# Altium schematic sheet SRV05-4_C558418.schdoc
size 127 x 101 mm
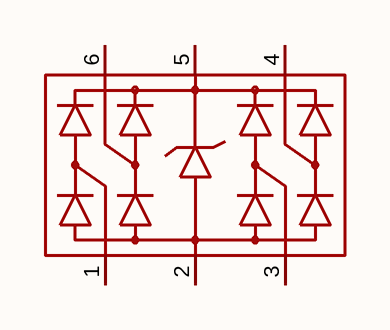
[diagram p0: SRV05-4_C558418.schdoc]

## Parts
D?  srv05-4_c558418  [SOT-23-6_L2.9-W1.6-P0.95-LS2.8-BL]  (value not drawn)

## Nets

Not connected (* = marked no-connect by the designer): D? 1 2 3 4 5 6

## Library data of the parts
D? = srv05-4_c558418: 极性:单向;反向截止电压(Vrwm):5V;钳位电压:20V;峰值脉冲电流(Ipp):3A;峰值脉冲功率(Ppp):60W;击穿电压:6V;; Manufacturer: TECH PUBLIC(台舟); AddInBom: yes; ModelId: 18da8f6c14a34920b3e136b5c401a119; ModelName: SOT-23-6_L2.9-W1.6-H1.5-LS2.8-P0.95; ModelTransform: 110.236,113.364,0,90,0,0,0.0005,0.0005,0; Polarity: 单向; Reverse Stand-Off Voltage (Vrwm): 5V; Clamping Voltage: 20V; Peak Pulse Current (Ipp): 3A; Peak Pulse Power Dissipation (Ppp): 60W; Voltage - Breakdown: 6V; Reverse Leakage Current (Ir): 500nA; Number of Channels: 四路; level of protection: IEC 61000-4-2；IEC 61000-4-4；IEC 61000-4-5; Type: ESD; Junction Capacitance: 0.8pF；0.3pF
